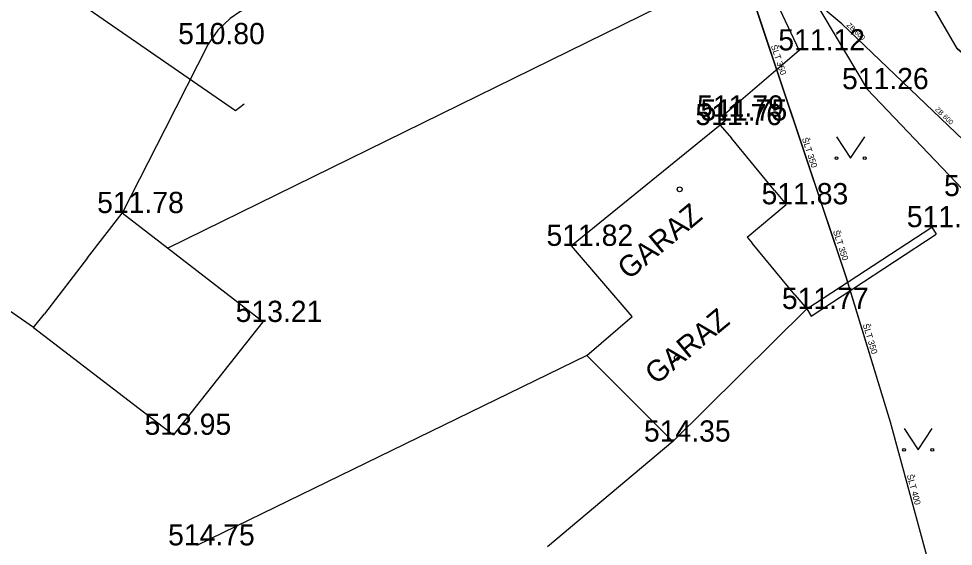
# Model space of a CAD drawing. Extents: x -669642 to -669119, y -1131006 to -1130466.
# Drawn here: x -669399.17 to -669366.1, y -1130974.62 to -1130955.97 of the extents above; entities that cross this region are included whole.
import ezdxf

# ---------------------------------------------------------------- set-up
doc = ezdxf.new("R2010")
doc.units = 0
for name, color, linetype in [('G_Bod_tecka', 7, 'Continuous'), ('G_Bod_vyska', 7, 'Continuous'), ('G_Breh_Teren', 7, 'Continuous'), ('G_Budovy-znacky', 7, 'Continuous'), ('G_Budovy_Objekty', 7, 'Continuous'), ('G_Budovy_vstupy', 7, 'Continuous'), ('G_Plochy_zpevnene', 7, 'Continuous'), ('G_Ploty', 7, 'Continuous'), ('G_Popisy_objektu', 7, 'Continuous'), ('G_Z_KANAL_podz_kotovane', 7, 'Continuous'), ('G_Z_SPOJE_nadz_kotovane', 7, 'Continuous'), ('G_Z_VODA_podz_kotovane', 7, 'Continuous'), ('G_Zelen-Znacky', 7, 'Continuous'), ('Vrstva 13', 7, 'Continuous'), ('Vrstva 26', 7, 'Continuous'), ('Vrstva 3', 7, 'Continuous'), ('Vrstva 4', 7, 'Continuous')]:
    doc.layers.add(name, color=color, linetype=linetype)

msp = doc.modelspace()

# ---------------------------------------------------------------- linework, layer by layer
at = {"layer": 'G_Bod_tecka'}
for p, q in [((-669392.46, -1130956.87), (-669392.46, -1130956.87)), ((-669371.55, -1130957.09), (-669371.55, -1130957.09)), ((-669369.14, -1130958.46), (-669369.14, -1130958.46)), ((-669374.28, -1130959.43), (-669374.28, -1130959.43)), ((-669374.34, -1130959.73), (-669374.34, -1130959.73)), ((-669374.16, -1130959.57), (-669374.16, -1130959.57)), ((-669372, -1130962.53), (-669372, -1130962.53)), ((-669395.51, -1130962.84), (-669395.51, -1130962.84)), ((-669366.86, -1130963.34), (-669366.86, -1130963.34)), ((-669379.61, -1130964), (-669379.61, -1130964)), ((-669371.28, -1130966.23), (-669371.28, -1130966.23)), ((-669390.53, -1130966.69), (-669390.53, -1130966.69)), ((-669393.69, -1130970.68), (-669393.69, -1130970.68)), ((-669376.02, -1130970.92), (-669376.02, -1130970.92)), ((-669392.86, -1130974.59), (-669392.86, -1130974.59))]:
    msp.add_line(p, q, dxfattribs=at)
at = {"layer": 'G_Breh_Teren'}
for p, q in [((-669393.9, -1130964.08), (-669373.07, -1130953.86)), ((-669379.06, -1130967.87), (-669392.86, -1130974.59))]:
    msp.add_line(p, q, dxfattribs=at)
msp.add_lwpolyline([(-669374.19, -1130951.48), (-669374.4, -1130951.55), (-669374.6, -1130951.62), (-669376.5, -1130952.21), (-669378.19, -1130952.63), (-669381.18, -1130953.22), (-669385.7, -1130954.04), (-669387.95, -1130954.55), (-669389.07, -1130954.85), (-669390.17, -1130955.19), (-669390.85, -1130955.47), (-669391.34, -1130955.73), (-669391.68, -1130955.96), (-669392.12, -1130956.38), (-669392.46, -1130956.87), (-669393.98, -1130959.86), (-669395.51, -1130962.84)], dxfattribs=at)
at = {"layer": 'G_Budovy-znacky'}
for centre in [(-669375.78, -1130962), (-669375.88, -1130967.96)]:
    msp.add_circle(centre, 0.0875, dxfattribs=at)
at = {"layer": 'G_Budovy_Objekty'}
for p, q in [((-669374.28, -1130959.43), (-669374.16, -1130959.57)), ((-669374.34, -1130959.73), (-669379.61, -1130964)), ((-669374.16, -1130959.57), (-669374.34, -1130959.73)), ((-669374.34, -1130959.73), (-669373.95, -1130960.19)), ((-669372.42, -1130962.04), (-669372.01, -1130962.54)), ((-669373.39, -1130963.69), (-669372.01, -1130962.54)), ((-669396.73, -1130964.42), (-669395.51, -1130962.84)), ((-669393.9, -1130964.08), (-669395.51, -1130962.84)), ((-669373.39, -1130963.69), (-669373.21, -1130963.9)), ((-669390.53, -1130966.69), (-669393.9, -1130964.08)), ((-669377.46, -1130966.5), (-669379.61, -1130964)), ((-669398.64, -1130966.89), (-669400.41, -1130965.66)), ((-669371.7, -1130965.73), (-669371.28, -1130966.23)), ((-669398.64, -1130966.89), (-669398.26, -1130966.4)), ((-669376.02, -1130970.92), (-669371.28, -1130966.23)), ((-669390.53, -1130966.69), (-669393.69, -1130970.68)), ((-669379.06, -1130967.87), (-669377.46, -1130966.5)), ((-669398.64, -1130966.89), (-669393.69, -1130970.68)), ((-669379.06, -1130967.87), (-669376.02, -1130970.92))]:
    msp.add_line(p, q, dxfattribs=at)
at = {"layer": 'G_Budovy_vstupy'}
for p, q in [((-669372.42, -1130962.04), (-669373.95, -1130960.19)), ((-669371.7, -1130965.73), (-669373.21, -1130963.9)), ((-669396.73, -1130964.42), (-669398.26, -1130966.4))]:
    msp.add_line(p, q, dxfattribs=at)
at = {"layer": 'G_Plochy_zpevnene'}
for p, q in [((-669374.87, -1130948.85), (-669369.14, -1130958.46)), ((-669369.14, -1130958.46), (-669365.53, -1130962.24)), ((-669371.28, -1130966.23), (-669366.86, -1130963.34)), ((-669366.86, -1130963.34), (-669366.7, -1130963.59)), ((-669371.12, -1130966.48), (-669366.7, -1130963.59)), ((-669371.28, -1130966.23), (-669371.12, -1130966.48))]:
    msp.add_line(p, q, dxfattribs=at)
at = {"layer": 'G_Ploty'}
for p, q in [((-669373.07, -1130953.86), (-669371.55, -1130957.09)), ((-669371.55, -1130957.09), (-669374.28, -1130959.43)), ((-669376.02, -1130970.92), (-669380.46, -1130974.64))]:
    msp.add_line(p, q, dxfattribs=at)
at = {"layer": 'G_Z_KANAL_podz_kotovane'}
msp.add_lwpolyline([(-669315.39, -1131000.6), (-669345.26, -1130979.82), (-669370.04, -1130956.15), (-669376.06, -1130951.12), (-669376.44, -1130950.62), (-669381.99, -1130913.61), (-669382.19, -1130912.29)], dxfattribs=at)
at = {"layer": 'G_Z_SPOJE_nadz_kotovane'}
msp.add_lwpolyline([(-669406.39, -1130948.94), (-669391.5, -1130959.21), (-669391.19, -1130958.98)], dxfattribs=at)
at = {"layer": 'G_Z_VODA_podz_kotovane'}
for points in [[(-669391.66, -1130786.81), (-669388.98, -1130811.25), (-669386.68, -1130832.57), (-669385.37, -1130847.78), (-669384.56, -1130852.58), (-669384.56, -1130855.1), (-669381.69, -1130881.23), (-669380.22, -1130906.82), (-669380.35, -1130922.88), (-669379.95, -1130930.64), (-669376.8, -1130944.92), (-669375.17, -1130949.36), (-669369.9, -1130965.09), (-669368.33, -1130970.22)], [(-669307.945, -1131000.6), (-669314.48, -1130996.96), (-669320.35, -1130993.41), (-669321.28, -1130992.94), (-669327.74, -1130988.8), (-669333.55, -1130984.56), (-669356.07, -1130965.69), (-669365.96, -1130957.03), (-669367.51, -1130954.34), (-669368.85, -1130951.75)], [(-669368.33, -1130970.22), (-669366.35, -1130977.5), (-669364.59, -1130981.99), (-669363.1, -1130986.58), (-669362.17, -1130990.98), (-669360.67, -1130995.88), (-669359.32, -1131000.41), (-669359.259, -1131000.6)]]:
    msp.add_lwpolyline(points, dxfattribs=at)
at = {"layer": 'G_Zelen-Znacky'}
for p, q in [((-669370.23, -1130960.15), (-669369.73, -1130960.9)), ((-669369.73, -1130960.9), (-669369.23, -1130960.15)), ((-669367.84, -1130970.46), (-669367.34, -1130971.21)), ((-669367.34, -1130971.21), (-669366.84, -1130970.46))]:
    msp.add_line(p, q, dxfattribs=at)
for centre in [(-669370.23, -1130960.9), (-669369.23, -1130960.9), (-669367.84, -1130971.21), (-669366.84, -1130971.21)]:
    msp.add_circle(centre, 0.05, dxfattribs=at)
at = {"layer": 'Vrstva 13'}
msp.add_lwpolyline([(-669315.39, -1131000.6), (-669345.261, -1130979.82), (-669370.044, -1130956.15), (-669376.06, -1130951.12), (-669376.436, -1130950.621), (-669381.993, -1130913.614), (-669382.192, -1130912.286)], dxfattribs=at)
at = {"layer": 'Vrstva 26'}
for points in [[(-669391.664, -1130786.81), (-669388.978, -1130811.253), (-669386.678, -1130832.566), (-669385.369, -1130847.782), (-669384.56, -1130852.58), (-669384.564, -1130855.105), (-669381.694, -1130881.226), (-669380.223, -1130906.82), (-669380.349, -1130922.883), (-669379.945, -1130930.641), (-669376.8, -1130944.921), (-669375.165, -1130949.355), (-669369.897, -1130965.087), (-669368.329, -1130970.216)], [(-669307.944, -1131000.6), (-669314.477, -1130996.96), (-669320.348, -1130993.408), (-669321.282, -1130992.94), (-669327.737, -1130988.804), (-669333.553, -1130984.562), (-669356.073, -1130965.685), (-669365.963, -1130957.028), (-669367.511, -1130954.339), (-669368.85, -1130951.75)], [(-669368.329, -1130970.216), (-669366.35, -1130977.5), (-669364.59, -1130981.99), (-669363.1, -1130986.58), (-669362.17, -1130990.98), (-669360.67, -1130995.88), (-669359.32, -1131000.41), (-669359.259, -1131000.6)]]:
    msp.add_lwpolyline(points, dxfattribs=at)

# ---------------------------------------------------------------- texts
at = {"layer": 'G_Bod_vyska'}
for s, p in [('510.80', (-669393.526, -1130956.87)), ('511.12', (-669372.289, -1130957.09)), ('511.26', (-669370.034, -1130958.46)), ('511.79', (-669375.163, -1130959.43)), ('511.75', (-669375.041, -1130959.57)), ('511.76', (-669375.224, -1130959.73)), ('511.62', (-669366.424, -1130962.24)), ('511.83', (-669372.881, -1130962.53)), ('511.78', (-669396.391, -1130962.84)), ('511.78', (-669367.741, -1130963.34)), ('511.82', (-669380.491, -1130964)), ('511.77', (-669372.161, -1130966.23)), ('513.21', (-669391.491, -1130966.69)), ('513.95', (-669394.714, -1130970.68)), ('514.35', (-669377.042, -1130970.92)), ('514.75', (-669393.882, -1130974.59))]:
    msp.add_text(s, height=0.75, dxfattribs=at).set_placement(p)
at = {"layer": 'G_Popisy_objektu'}
for p in [(-669377.585, -1130965.223), (-669376.615, -1130968.933)]:
    msp.add_text('GARAZ', height=0.75, rotation=39.5796, dxfattribs=at).set_placement(p)
at = {"layer": 'Vrstva 3'}
for rotation, p in [(317.1657, (-669369.883, -1130956.217)), (316.3336, (-669366.756, -1130959.193))]:
    msp.add_text('ZB 600', height=0.1755, rotation=rotation, dxfattribs=at).set_placement(p)
at = {"layer": 'Vrstva 4'}
for s, rotation, p in [('ŠLT 350', 288.4758, (-669372.554, -1130956.931)), ('ŠLT 350', 288.4758, (-669371.456, -1130960.21)), ('ŠLT 350', 288.5075, (-669370.358, -1130963.489)), ('ŠLT 350', 287.0057, (-669369.304, -1130966.784)), ('ŠLT 400', 285.2438, (-669367.743, -1130972.106))]:
    msp.add_text(s, height=0.2194, rotation=rotation, dxfattribs=at).set_placement(p)

doc.saveas('drawing.dxf')
